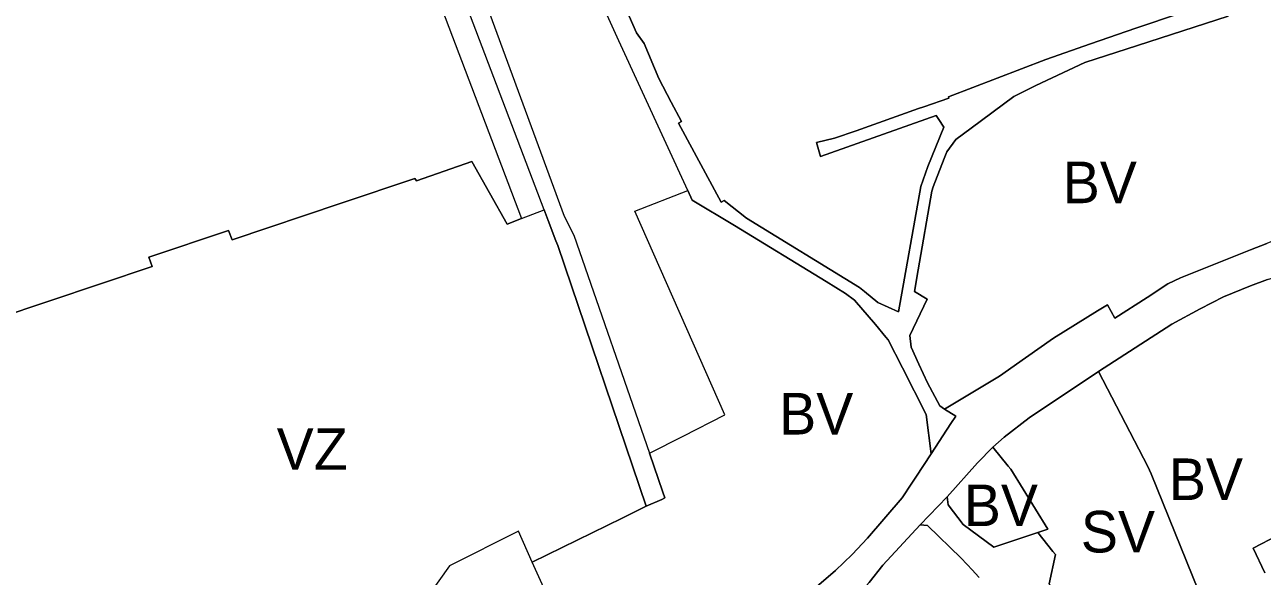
# Model space of a CAD drawing. Extents: x -650451 to -642268, y -1075216 to -1066610.
# Drawn here: x -648639 to -648281.9, y -1067264.6 to -1067105.4 of the extents above; entities that cross this region are included whole.
import ezdxf

# ---------------------------------------------------------------- set-up
doc = ezdxf.new("R2010")
doc.units = 0
doc.header["$LTSCALE"] = 4.8
for name, color, linetype, lineweight in [('15', 7, 'Continuous', 13), ('19', 7, 'Continuous', 13), ('24', 7, 'Continuous', 13), ('3', 7, 'Continuous', 13), ('36', 7, 'Continuous', 13), ('45', 7, 'Continuous', 13), ('46', 7, 'Continuous', 13)]:
    doc.layers.add(name, color=color, linetype=linetype, lineweight=lineweight)
doc.layers.add('62', color=7, linetype='Continuous')

msp = doc.modelspace()

# ---------------------------------------------------------------- linework, layer by layer
at = {"layer": '15'}
msp.add_line((-648380.63, -1067249.79), (-648372.85, -1067241.63), dxfattribs=at)
for points in [[(-648447.66, -1067153.25), (-648467.56, -1067110.02), (-648490.23, -1067060.06), (-648496.87, -1067053.5), (-648506.78, -1067037.81), (-648514.38, -1067016.2), (-648513.842, -1066960.243)], [(-648482.9, -1067061.25), (-648462.48, -1067107.73), (-648460.23, -1067110.8), (-648456.07, -1067120.9), (-648452.42, -1067127.79), (-648449.5, -1067133.31), (-648450.39, -1067133.79), (-648438.06, -1067156.58), (-648437.18, -1067156.12), (-648430.77, -1067161.23), (-648398.15, -1067181.21), (-648396.64, -1067182.42), (-648392.85, -1067185.57), (-648386.89, -1067188.24), (-648380.45, -1067152.1), (-648378.37, -1067146.35), (-648373.77, -1067134.94), (-648375.2, -1067132.77), (-648375.96, -1067131.6), (-648409.41, -1067143.46), (-648410.57, -1067139.42), (-648405.38, -1067138.16), (-648399.11, -1067136.06), (-648381.11, -1067129.62), (-648379.52, -1067129.08), (-648372.38, -1067126.64), (-648372.47, -1067126.23), (-648344.37, -1067115.45), (-648331.48, -1067110.95), (-648318.38, -1067106.37), (-648305.53, -1067102.05)], [(-648291.72, -1067102.95), (-648317.87, -1067111.36), (-648333.15, -1067116.28), (-648347.24, -1067122.96), (-648352.62, -1067125.63), (-648353.6, -1067126.12), (-648365.94, -1067135.24), (-648370.34, -1067138.49), (-648372.9, -1067142.04), (-648373.74, -1067143.99), (-648376.85, -1067152.17), (-648377.25, -1067153.46), (-648381.2, -1067176.15), (-648382.29, -1067182.39), (-648378.59, -1067184.6), (-648383.59, -1067195.09), (-648383.19, -1067198.5), (-648381, -1067203.33), (-648378.54, -1067208.75), (-648374.98, -1067215.4), (-648373.57, -1067216.32)], [(-648377.49, -1067229.27), (-648378.85, -1067217.89), (-648385.7, -1067204.45), (-648389.88, -1067196.34), (-648390.51, -1067195.57), (-648393.47, -1067191.93), (-648399.53, -1067184.85), (-648402.18, -1067182.95), (-648407.75, -1067179.54), (-648434.22, -1067163.35), (-648446.4, -1067155.99), (-648447.66, -1067153.25)], [(-648373.57, -1067216.32), (-648370.35, -1067218.41), (-648371.74, -1067220.52), (-648377.49, -1067229.27)], [(-648372.85, -1067241.63), (-648372.55, -1067244), (-648368.18, -1067249.63), (-648359.37, -1067256.17), (-648346.63, -1067251.93)], [(-648363.62, -1067264.94), (-648364.71, -1067263.65), (-648365.5, -1067262.82), (-648368.76, -1067259.41), (-648378.53, -1067249.9), (-648380.63, -1067249.79)], [(-648346.63, -1067251.93), (-648342.33, -1067257.4), (-648341.58, -1067258.35), (-648343.39, -1067266.77), (-648335.18, -1067281.15), (-648330.35, -1067289.62)], [(-648281.13, -1067263.61), (-648284.52, -1067256.43), (-648277.56, -1067252.8)]]:
    msp.add_lwpolyline(points, dxfattribs=at)
at = {"layer": '19'}
for points in [[(-648359.67, -1067227.37), (-648356.41, -1067224.48), (-648349.21, -1067218.88), (-648329.21, -1067205.45)], [(-648329.21, -1067205.45), (-648314.95, -1067232.87), (-648313.93, -1067235.05), (-648298.68, -1067272.86), (-648307.89, -1067277.74), (-648314.34, -1067281.15), (-648330.35, -1067289.62)], [(-648346.63, -1067251.93), (-648343.83, -1067251), (-648354.49, -1067233.68), (-648355.21, -1067232.8), (-648359.67, -1067227.37)], [(-648330.35, -1067289.62), (-648335.18, -1067281.15), (-648343.39, -1067266.77), (-648341.58, -1067258.35), (-648342.33, -1067257.4), (-648346.63, -1067251.93)]]:
    msp.add_lwpolyline(points, dxfattribs=at)
at = {"layer": '24'}
for points in [[(-648326.59, -1067186.29), (-648324.45, -1067190.09), (-648315.08, -1067184.12), (-648309.13, -1067180.23), (-648305.51, -1067178.42), (-648285.34, -1067170.4), (-648280.63, -1067168.54)], [(-648280.44, -1067178.9), (-648285.27, -1067180.73), (-648293.08, -1067183.94), (-648299.88, -1067187.36)], [(-648373.57, -1067216.32), (-648357.72, -1067206.82), (-648350.22, -1067201.55), (-648342.17, -1067195.9), (-648329.48, -1067187.98), (-648326.59, -1067186.29)], [(-648299.88, -1067187.36), (-648308.01, -1067191.81), (-648329.21, -1067205.45)], [(-648329.21, -1067205.45), (-648349.21, -1067218.88), (-648356.41, -1067224.48), (-648359.67, -1067227.37), (-648364.06, -1067231.89), (-648372.85, -1067241.63), (-648380.63, -1067249.79)], [(-648377.49, -1067229.27), (-648371.74, -1067220.52), (-648370.35, -1067218.41), (-648373.57, -1067216.32)], [(-648383.03, -1067237.69), (-648381.86, -1067235.96), (-648377.49, -1067229.27)], [(-648415.01, -1067270.75), (-648411.21, -1067268.17), (-648405.09, -1067262.89), (-648400.28, -1067258.29), (-648395.86, -1067253.62), (-648385.77, -1067241.94), (-648383.03, -1067237.69)], [(-648380.63, -1067249.79), (-648391.39, -1067261.43), (-648395.3, -1067266.38), (-648403.22, -1067275.24)]]:
    msp.add_lwpolyline(points, dxfattribs=at)
at = {"layer": '3'}
for points in [[(-648305.53, -1067102.05), (-648318.38, -1067106.37), (-648331.48, -1067110.95), (-648344.37, -1067115.45), (-648372.47, -1067126.23), (-648372.38, -1067126.64), (-648379.52, -1067129.08), (-648381.11, -1067129.62), (-648399.11, -1067136.06), (-648405.38, -1067138.16), (-648410.57, -1067139.42), (-648409.41, -1067143.46), (-648375.96, -1067131.6), (-648375.2, -1067132.77), (-648373.77, -1067134.94), (-648378.37, -1067146.35), (-648380.45, -1067152.1), (-648386.89, -1067188.24), (-648392.85, -1067185.57), (-648396.64, -1067182.42), (-648398.15, -1067181.21), (-648430.77, -1067161.23), (-648437.18, -1067156.12), (-648438.06, -1067156.58), (-648450.39, -1067133.79), (-648449.5, -1067133.31), (-648452.42, -1067127.79), (-648456.07, -1067120.9), (-648460.23, -1067110.8), (-648462.48, -1067107.73), (-648482.9, -1067061.25)], [(-648373.57, -1067216.32), (-648374.98, -1067215.4), (-648378.54, -1067208.75), (-648381, -1067203.33), (-648383.19, -1067198.5), (-648383.59, -1067195.09), (-648378.59, -1067184.6), (-648382.29, -1067182.39), (-648381.2, -1067176.15), (-648377.25, -1067153.46), (-648376.85, -1067152.17), (-648373.74, -1067143.99), (-648372.9, -1067142.04), (-648370.34, -1067138.49), (-648365.94, -1067135.24), (-648353.6, -1067126.12), (-648352.62, -1067125.63), (-648347.24, -1067122.96), (-648333.15, -1067116.28), (-648317.87, -1067111.36), (-648291.72, -1067102.95)], [(-648458.73, -1067229.1), (-648449.03, -1067224.14), (-648437.02, -1067217.99), (-648462.97, -1067159.24), (-648447.66, -1067153.25)], [(-648447.66, -1067153.25), (-648446.4, -1067155.99), (-648434.22, -1067163.35), (-648407.75, -1067179.54), (-648402.18, -1067182.95), (-648399.53, -1067184.85), (-648393.47, -1067191.93), (-648390.51, -1067195.57), (-648389.88, -1067196.34), (-648385.7, -1067204.45), (-648378.85, -1067217.89), (-648377.49, -1067229.27)], [(-648265.69, -1067158.05), (-648266.18, -1067159.3), (-648268.87, -1067162.19), (-648270.63, -1067163.83), (-648273.82, -1067165.52), (-648276.15, -1067166.76), (-648280.63, -1067168.54), (-648285.34, -1067170.4), (-648305.51, -1067178.42)], [(-648305.51, -1067178.42), (-648309.13, -1067180.23), (-648315.08, -1067184.12), (-648324.45, -1067190.09), (-648326.59, -1067186.29), (-648329.48, -1067187.98), (-648342.17, -1067195.9), (-648350.22, -1067201.55)], [(-648293.08, -1067183.94), (-648285.27, -1067180.73), (-648280.44, -1067178.9), (-648275.53, -1067177.49), (-648271.57, -1067176.46)], [(-648329.21, -1067205.45), (-648308.01, -1067191.81), (-648299.88, -1067187.36), (-648293.08, -1067183.94)], [(-648350.22, -1067201.55), (-648357.72, -1067206.82), (-648373.57, -1067216.32)], [(-648330.35, -1067289.62), (-648314.34, -1067281.15), (-648307.89, -1067277.74), (-648298.68, -1067272.86), (-648313.93, -1067235.05), (-648314.95, -1067232.87), (-648329.21, -1067205.45)], [(-648459.64, -1067244.34), (-648455.15, -1067242.39), (-648454.27, -1067241.92), (-648454.83, -1067240.34), (-648458.73, -1067229.1)], [(-648377.49, -1067229.27), (-648381.86, -1067235.96), (-648383.03, -1067237.69), (-648385.77, -1067241.94)], [(-648372.85, -1067241.63), (-648364.06, -1067231.89), (-648359.67, -1067227.37)], [(-648359.67, -1067227.37), (-648355.21, -1067232.8), (-648354.49, -1067233.68), (-648343.83, -1067251), (-648346.63, -1067251.93)], [(-648385.77, -1067241.94), (-648395.86, -1067253.62), (-648400.28, -1067258.29), (-648405.09, -1067262.89), (-648411.21, -1067268.17), (-648415.01, -1067270.75)], [(-648346.63, -1067251.93), (-648359.37, -1067256.17), (-648368.18, -1067249.63), (-648372.55, -1067244), (-648372.85, -1067241.63)], [(-648492.62, -1067260.53), (-648466.58, -1067247.78), (-648459.64, -1067244.34)], [(-648395.3, -1067266.38), (-648391.39, -1067261.43), (-648380.63, -1067249.79)], [(-648380.63, -1067249.79), (-648378.53, -1067249.9), (-648368.76, -1067259.41), (-648365.5, -1067262.82), (-648364.71, -1067263.65), (-648363.62, -1067264.94)], [(-648277.56, -1067252.8), (-648284.52, -1067256.43), (-648281.13, -1067263.61)], [(-648474.69, -1067299.66), (-648485.16, -1067276.83), (-648486.79, -1067273.26), (-648492.62, -1067260.53)]]:
    msp.add_lwpolyline(points, dxfattribs=at)
at = {"layer": '36'}
for points in [[(-648691.66, -1067224.94), (-648697.59, -1067207.11), (-648676.84, -1067200.16), (-648602.26, -1067175.2), (-648603.17, -1067172.45), (-648580.15, -1067164.76), (-648579.12, -1067167.45), (-648547.68, -1067156.93), (-648526.39, -1067149.8), (-648525.95, -1067150.5), (-648510.01, -1067144.84), (-648499.79, -1067162.97), (-648495.63, -1067161.363), (-648489.1, -1067158.84)], [(-648489.1, -1067158.84), (-648487.92, -1067161.94), (-648485.74, -1067167.74), (-648485.2, -1067169.09), (-648459.64, -1067244.34)], [(-648459.64, -1067244.34), (-648466.58, -1067247.78), (-648492.62, -1067260.53)], [(-648492.62, -1067260.53), (-648496.55, -1067251.53), (-648516.47, -1067261.54), (-648536.84, -1067290.29), (-648547.17, -1067296.68), (-648531.51, -1067337.57), (-648539.73, -1067345.03)]]:
    msp.add_lwpolyline(points, dxfattribs=at)
at = {"layer": '45'}
for points in [[(-648651.1, -1066669.56), (-648619.11, -1066742.12), (-648582.52, -1066816.7), (-648569.13, -1066848.61), (-648566.63, -1066856.72), (-648563.48, -1066866.96), (-648560.2, -1066888.58), (-648528.01, -1067023.13), (-648518.72, -1067061.99), (-648514.86, -1067074.83), (-648507.88, -1067093.9), (-648483.31, -1067160.63), (-648480.57, -1067166.13), (-648458.73, -1067229.1)], [(-648489.1, -1067158.84), (-648512.95, -1067095.97), (-648520.4, -1067077.42), (-648524.93, -1067063.35), (-648533.66, -1067026), (-648551, -1066951.85), (-648564.4, -1066894.52), (-648571.96, -1066869.37)], [(-648459.64, -1067244.34), (-648485.2, -1067169.09), (-648485.74, -1067167.74), (-648487.92, -1067161.94), (-648489.1, -1067158.84)], [(-648458.73, -1067229.1), (-648454.83, -1067240.34), (-648454.27, -1067241.92), (-648455.15, -1067242.39), (-648459.64, -1067244.34)]]:
    msp.add_lwpolyline(points, dxfattribs=at)
at = {"layer": '46'}
for points in [[(-648583.94, -1066851.11), (-648578.702, -1066871.259), (-648571.167, -1066896.326), (-648557.816, -1066953.444), (-648540.476, -1067027.594), (-648531.681, -1067065.222), (-648526.988, -1067079.8), (-648519.471, -1067098.516), (-648495.63, -1067161.363)], [(-648495.63, -1067161.363), (-648499.79, -1067162.97), (-648510.01, -1067144.84), (-648525.95, -1067150.5), (-648526.39, -1067149.8), (-648547.68, -1067156.93), (-648579.12, -1067167.45), (-648580.15, -1067164.76), (-648603.17, -1067172.45), (-648602.26, -1067175.2), (-648676.84, -1067200.16), (-648697.59, -1067207.11), (-648691.66, -1067224.94)]]:
    msp.add_lwpolyline(points, dxfattribs=at)

# ---------------------------------------------------------------- texts
at = {"layer": '62'}
for s, p in [('BV', (-648339.49, -1067156.911)), ('BV', (-648421.321, -1067223.671)), ('VZ', (-648566.295, -1067233.862)), ('BV', (-648308.878, -1067242.584)), ('BV', (-648368.039, -1067250.104)), ('SV', (-648334.258, -1067257.711))]:
    msp.add_text(s, height=12, dxfattribs=at).set_placement(p)

doc.saveas('drawing.dxf')
